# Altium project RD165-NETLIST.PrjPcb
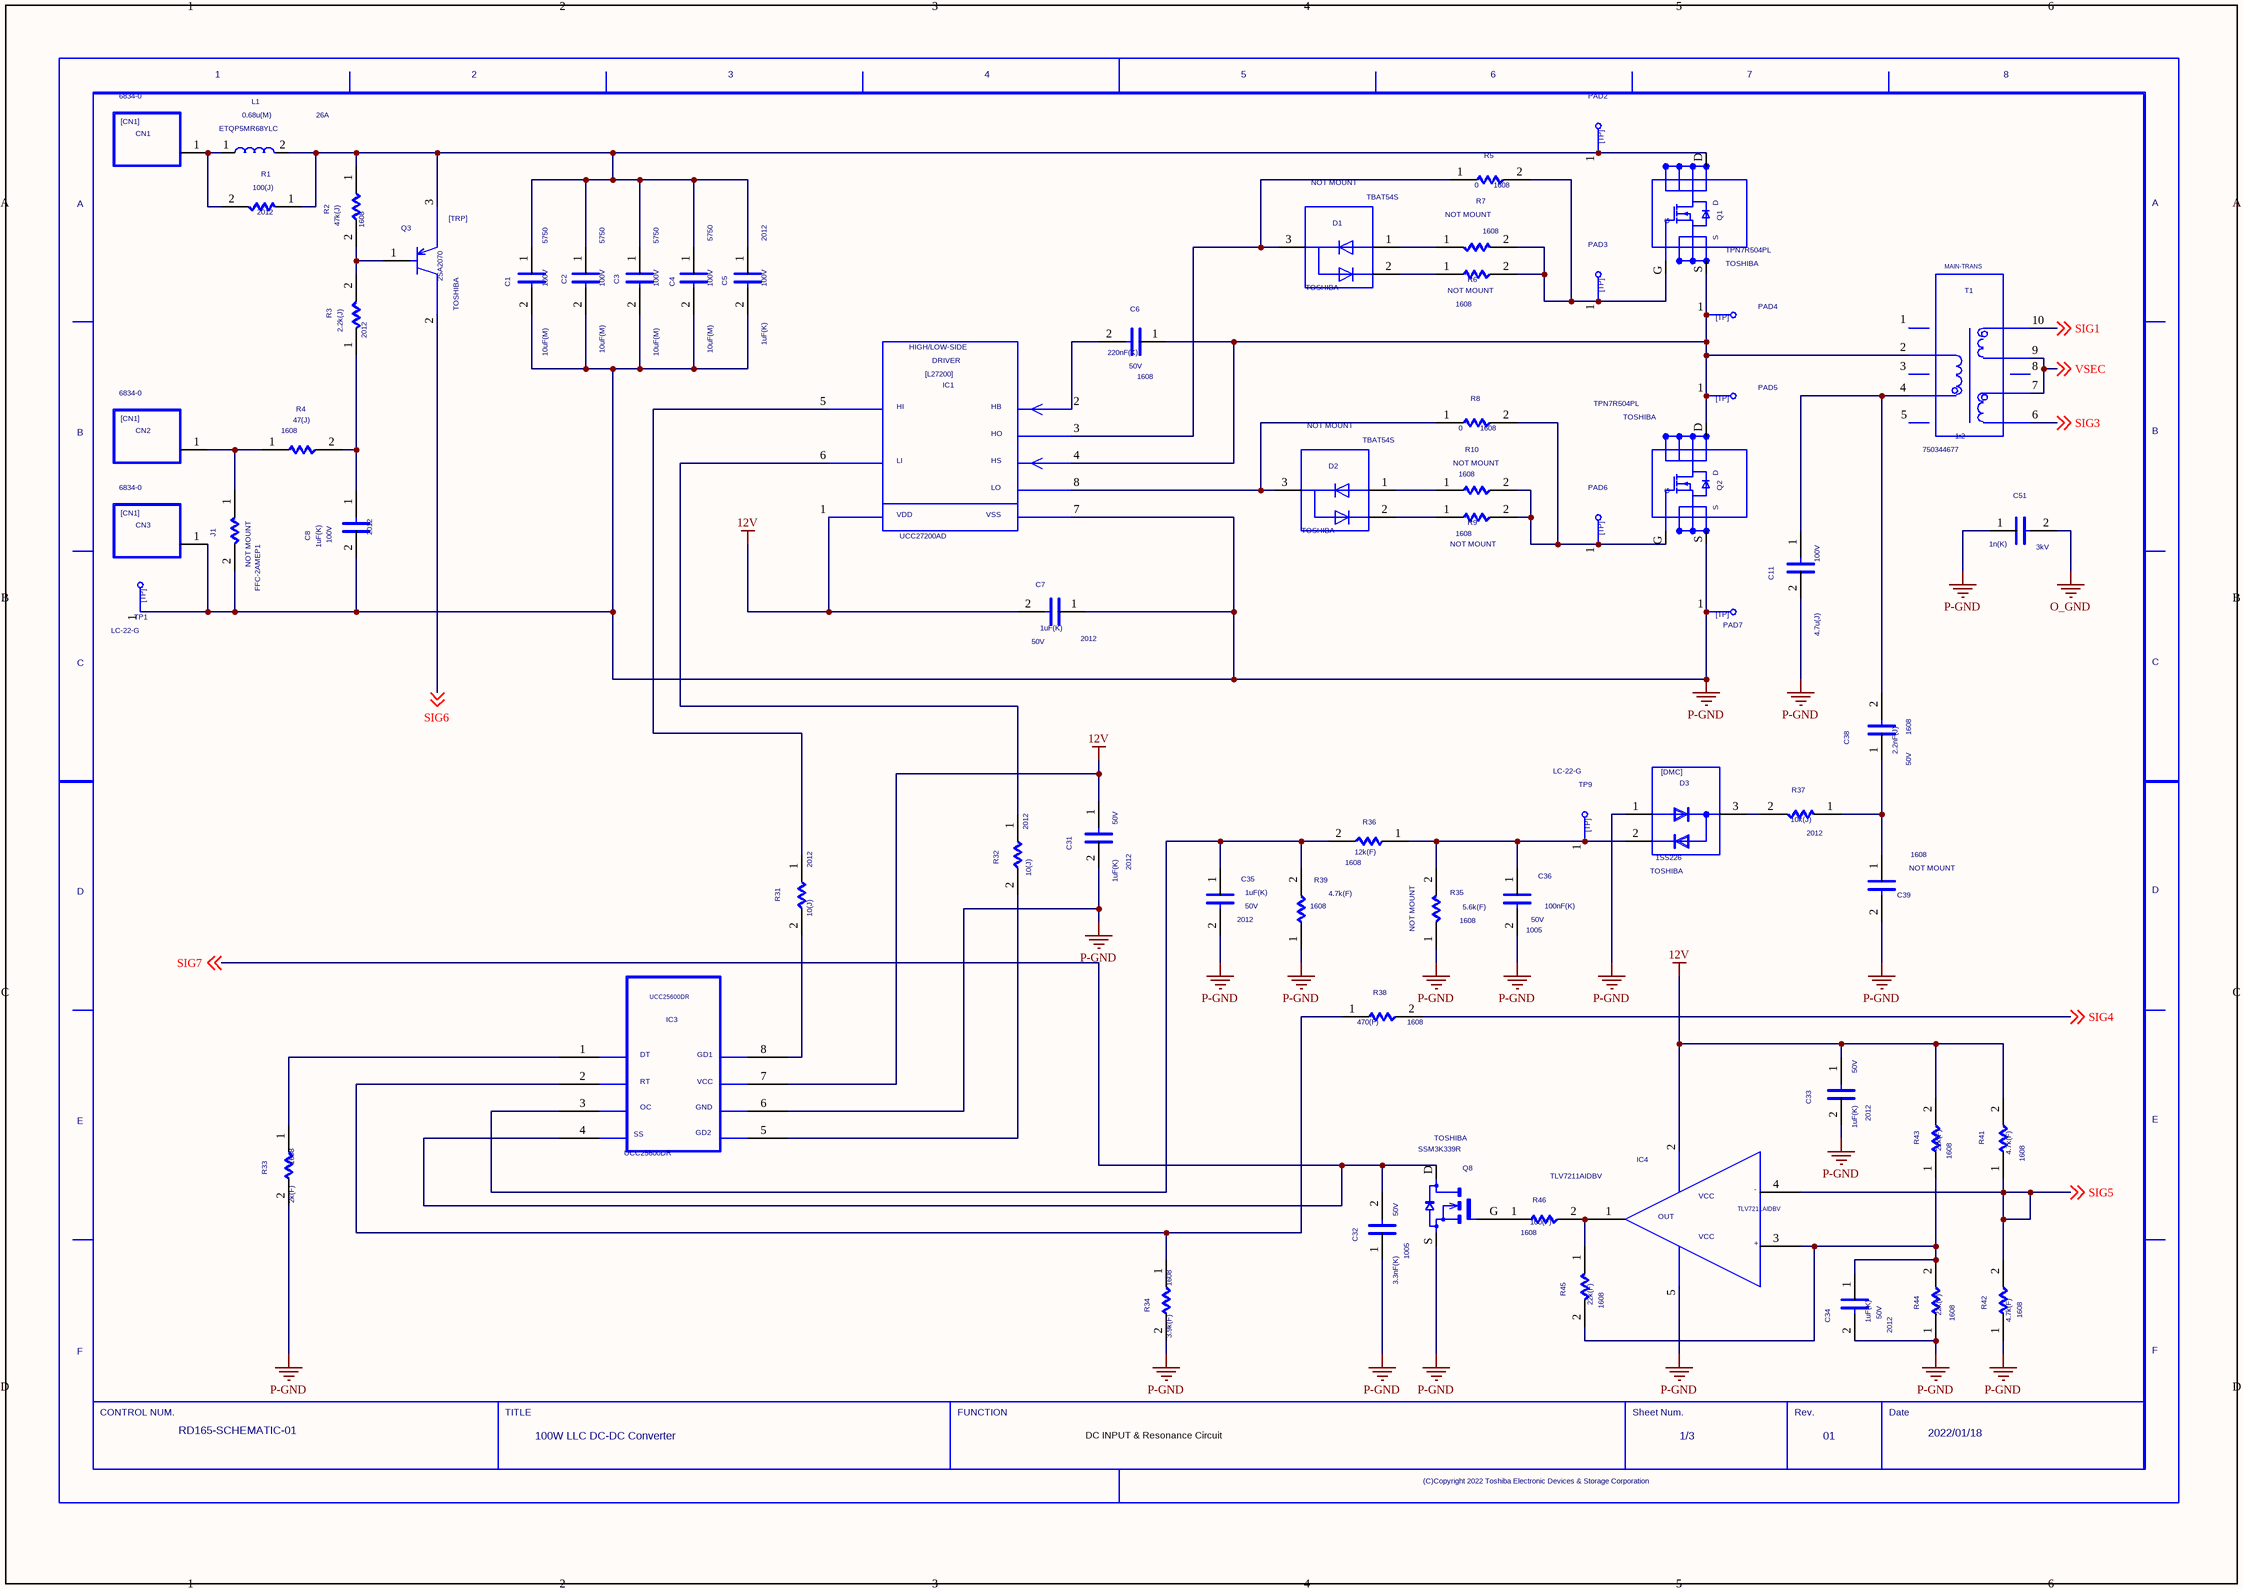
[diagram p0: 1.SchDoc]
3 sheets, 144 parts. Net scope: global (net labels, ports and power ports of the same name join across sheets).
Sheets:
  1.SchDoc
  2.SchDoc
  3.SchDoc

## Sheet 1.SchDoc
size 420 x 297 mm

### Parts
(Parts that share a designator on the sheet are numbered #1, #2 ... from top to bottom, then left to right.)
C1  SIZECODESMD: 5750  VAL2: 100V  VAL1: 10uF(M)  (hidden comment: C)
C2  SIZECODESMD: 5750  VAL2: 100V  VAL1: 10uF(M)  (hidden comment: C)
C3  SIZECODESMD: 5750  VAL2: 100V  VAL1: 10uF(M)  (hidden comment: C)
C4  SIZECODESMD: 5750  VAL2: 100V  VAL1: 10uF(M)  (hidden comment: C)
C5  SIZECODESMD: 2012  VAL2: 100V  VAL1: 1uF(K)  (hidden comment: C)
C6  SIZECODESMD: 1608  VAL2: 50V  VAL1: 220nF(K)  (hidden comment: C)
C7  SIZECODESMD: 2012  VAL2: 50V  VAL1: 1uF(K)  (hidden comment: C)
C8  SIZECODESMD: 2012  VAL2: 100V  VAL1: 1uF(K)  (hidden comment: C)
C11  VAL2: 100V  VAL1: 4.7u(J)  (hidden comment: C)
C31  SIZECODESMD: 2012  VAL2: 50V  VAL1: 1uF(K)  (hidden comment: C)
C32  SIZECODESMD: 1005  VAL2: 50V  VAL1: 3.3nF(K)  (hidden comment: C)
C33  SIZECODESMD: 2012  VAL2: 50V  VAL1: 1uF(K)  (hidden comment: C)
C34  SIZECODESMD: 2012  VAL2: 50V  VAL1: 1uF(K)  (hidden comment: C)
C35  SIZECODESMD: 2012  VAL2: 50V  VAL1: 1uF(K)  (hidden comment: C)
C36  SIZECODESMD: 1005  VAL2: 50V  VAL1: 100nF(K)  (hidden comment: C)
C38  SIZECODESMD: 1608  VAL2: 50V  VAL1: 2.2nF(J)  (hidden comment: C)
C39  NOTMOUNT: NOT MOUNT  SIZECODESMD: 1608  (hidden comment: C)
C51  VAL2: 3kV  VAL1: 1n(K)  (hidden comment: C)
CN1  VAL3: 6834-0  (hidden comment: CN1)
CN2  VAL3: 6834-0  (hidden comment: CN1)
CN3  VAL3: 6834-0  (hidden comment: CN1)
D1  USERCOMPTEXT3: TOSHIBA  NOTMOUNT: NOT MOUNT  (hidden comment: TBAT54S)
D2  USERCOMPTEXT3: TOSHIBA  NOTMOUNT: NOT MOUNT  (hidden comment: TBAT54S)
D3  USERCOMPTEXT3: TOSHIBA  VAL3: 1SS226  (hidden comment: DMC)
IC1  VAL3: UCC27200AD  (hidden comment: L27200)
IC3  UCC25600DR
IC4  TLV7211AIDBV
J1  VAL3: FFC-2AMEP1  NOTMOUNT: NOT MOUNT  (hidden comment: R)
L1  VAL3: ETQP5MR68YLC  VAL2: 26A  VAL1: 0.68u(M)  (hidden comment: L)
PAD2  TP  (value not drawn)
PAD3  TP  (value not drawn)
PAD4  TP  (value not drawn)
PAD5  TP  (value not drawn)
PAD6  TP  (value not drawn)
PAD7  TP  (value not drawn)
Q1  USERCOMPTEXT3: TOSHIBA  VAL3: TPN7R504PL  (hidden comment: TPN7B504PL)
Q2  USERCOMPTEXT3: TOSHIBA  VAL3: TPN7R504PL  (hidden comment: TPN7B504PL)
Q3  USERCOMPTEXT3: TOSHIBA  VAL3: 2SA2070  (hidden comment: TRP)
Q8  USERCOMPTEXT3: TOSHIBA  VAL3: SSM3K339R  (hidden comment: MFNF)
R1  SIZECODESMD: 2012  VAL1: 100(J)  (hidden comment: R)
R2  SIZECODESMD: 1608  VAL1: 47k(J)  (hidden comment: R)
R3  SIZECODESMD: 2012  VAL1: 2.2k(J)  (hidden comment: R)
R4  SIZECODESMD: 1608  VAL1: 47(J)  (hidden comment: R)
R5  SIZECODESMD: 1608  VAL1: 0  (hidden comment: R)
R6  NOTMOUNT: NOT MOUNT  SIZECODESMD: 1608  (hidden comment: R)
R7  NOTMOUNT: NOT MOUNT  SIZECODESMD: 1608  (hidden comment: R)
R8  SIZECODESMD: 1608  VAL1: 0  (hidden comment: R)
R9  NOTMOUNT: NOT MOUNT  SIZECODESMD: 1608  (hidden comment: R)
R10  NOTMOUNT: NOT MOUNT  SIZECODESMD: 1608  (hidden comment: R)
R31  SIZECODESMD: 2012  VAL1: 10(J)  (hidden comment: R)
R32  SIZECODESMD: 2012  VAL1: 10(J)  (hidden comment: R)
R33  SIZECODESMD: 1608  VAL1: 2k(F)  (hidden comment: R)
R34  SIZECODESMD: 1608  VAL1: 3.9k(F)  (hidden comment: R)
R35  NOTMOUNT: NOT MOUNT  SIZECODESMD: 1608  VAL1: 5.6k(F)  (hidden comment: R)
R36  SIZECODESMD: 1608  VAL1: 12k(F)  (hidden comment: R)
R37  SIZECODESMD: 2012  VAL1: 10k(J)  (hidden comment: R)
R38  SIZECODESMD: 1608  VAL1: 470(F)  (hidden comment: R)
R39  SIZECODESMD: 1608  VAL1: 4.7k(F)  (hidden comment: R)
R41  SIZECODESMD: 1608  VAL1: 4.7k(F)  (hidden comment: R)
R42  SIZECODESMD: 1608  VAL1: 4.7k(F)  (hidden comment: R)
R43  SIZECODESMD: 1608  VAL1: 22k(F)  (hidden comment: R)
R44  SIZECODESMD: 1608  VAL1: 22k(F)  (hidden comment: R)
R45  SIZECODESMD: 1608  VAL1: 22k(F)  (hidden comment: R)
R46  SIZECODESMD: 1608  VAL1: 100(F)  (hidden comment: R)
T1  VAL1: 1:2  VAL3: 750344677  (hidden comment: TRANS)
TP1  VAL3: LC-22-G  (hidden comment: TP)
TP9  VAL3: LC-22-G  (hidden comment: TP)
U?#1  DATE: 2022/01/18  TITLE: 100W LLC DC-DC Converter  REVISION: 01  SHEETNUMBER: 1/3  DRAWINGNUMBER: RD165-SCHEMATIC-01  (hidden comment: WAKU_DEF100)

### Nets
O_GND: C51.2
SIG104: C7.2 C31.1 C33.1 IC1.1 IC3.7 IC4.2 R41.2 R43.2  [also labelled 12V, SIG130]
SIG267: C1.2 C2.2 C3.2 C4.2 C5.2 C7.1 C8.2 C11.2 C31.2 C32.1 C33.2 C34.2 C35.2 C36.2 C39.2 C51.1 CN3.1 D3.1(A) IC1.7 IC3.6 IC4.5 J1.2 PAD7.1 Q2.S Q8.S R33.2 R34.2 R35.1 R39.1 R42.1 R44.1 TP1.1  [also labelled P-GND, SIG268]
SIG270: T1.7 T1.9 ; off-sheet VSEC  [also labelled VSEC]  [project net SIG214]
DN000002: IC3.2 R34.1 R38.1
DN000007: C11.1 C38.2 T1.4
DN000046: IC3.1 R33.1
N04422: C1.1 C2.1 C3.1 C4.1 C5.1 L1.2 PAD2.1 Q1.D Q3.3(E) R1.1 R2.1
N216469: Q3.1(B) R2.2 R3.2
N216829: C8.1 R3.1 R4.2
N216837: CN2.1 J1.1 R4.1
SIG1: T1.10 ; off-sheet SIG1
SIG3: T1.6 ; off-sheet SIG3
SIG4: R38.2 ; off-sheet SIG4
SIG5: IC4.4 R41.1 R42.2 ; off-sheet SIG5
SIG6: Q3.2(C) ; off-sheet SIG6
SIG7: C32.2 IC3.4 Q8.D ; off-sheet SIG7
SIG67: IC3.8 R31.2
SIG85: C34.1 IC4.3 R43.1 R44.2 R45.2
SIG102: C38.1 C39.1 R37.1
SIG119: CN1.1 L1.1 R1.2
SIG125: D2.3 IC1.8 R8.1
SIG126: IC1.6 R32.1
SIG127: IC1.5 R31.1
SIG128: D1.3 IC1.3 R5.1
SIG129: C6.2 IC1.2
SIG131: C6.1 IC1.4 PAD4.1 PAD5.1 Q1.S Q2.D T1.2
SIG190: IC3.5 R32.2
SIG212: D3.3(AC) R37.2
SIG218: PAD3.1 Q1.G R5.2 R6.2 R7.2
SIG231: PAD6.1 Q2.G R8.2 R9.2 R10.2
SIG233: C36.1 D3.2(C) R35.2 R36.1 TP9.1
SIG237: D2.1 R10.1
SIG239: D1.2 R6.1
SIG240: IC4.1 R45.1 R46.2
SIG248: D1.1 R7.1
SIG249: D2.2 R9.1
SIG269: C35.1 IC3.3 R36.2 R39.2
NetQ8_G: Q8.G R46.1

Not connected (* = marked no-connect by the designer): T1 1 3 5 8

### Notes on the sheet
- DC INPUT & Resonance Circuit

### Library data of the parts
C1-C4 = C: OriginalSymbolOrigin: (2540,7620); RATEDVOLTAGE: 50; MAXGCOUNT: 1; TEMPCHARACTERI2: E; OUMEMAKER: KYC 京セラ; QUADMODEL: CON_10U; FNLEADFREETHET1GT2GMCTH1: N_N_N; OUMECLASSIFICATION: セラミックコンデンサ; CDBNAME: Chip5750_TD; NOMINALCAPACITA: 10u; OUMEMAKERKATAMEI: CX55Y5U106M50AT; CAPACITANCETOLE: M; CDMASTERCADCELG: DC848R; ADSMODELNAME: s_CX55Y5U106M50AT
C5 = C: OriginalSymbolOrigin: (2540,7620); RATEDVOLTAGE: 100; MAXGCOUNT: 1; OUMEMAKER: TDK ＴＤＫ; QUADMODEL: CON_1U; FNLEADFREETHET1GT2GMCTH1: 3_2_N; OUMECLASSIFICATION: セラミックコンデンサ; CDBNAME: Chip2012_GS_1; NOMINALCAPACITA: 1u; PMPRODUCTSTYPEG: HEV; OUMEMAKERKATAMEI: CGA4J3X7S2A105KT@@; CAPACITANCETOLE: K; CDMASTERCADCELG: KC0136; ADSMODELNAME: s_CGA4J3X7S2A105KT@@
C6 = C: OriginalSymbolOrigin: (2540,7620); RATEDVOLTAGE: 50; MAXGCOUNT: 1; OUMEMAKER: TDK ＴＤＫ; QUADMODEL: CON_220N; FNLEADFREETHET1GT2GMCTH1: N_N_N; OUMECLASSIFICATION: セラミックコンデンサ; CDBNAME: Chip1608_GS_1; NOMINALCAPACITA: 220n; PMPRODUCTSTYPEG: DA; OUMEMAKERKATAMEI: CGA3E3X7R1H224KT@@; CAPACITANCETOLE: K; CDMASTERCADCELG: KCK0238; ADSMODELNAME: s_CGA3E3X7R1H224KT@@
C7 C34 = C: OriginalSymbolOrigin: (2540,7620); RATEDVOLTAGE: 50; MAXGCOUNT: 1; OUMEMAKER: TDK ＴＤＫ; QUADMODEL: CON_1U; FNLEADFREETHET1GT2GMCTH1: 3_2_N; OUMECLASSIFICATION: セラミックコンデンサ; CDBNAME: Chip2012_GS_1; NOMINALCAPACITA: 1u; PMPRODUCTSTYPEG: DA; OUMEMAKERKATAMEI: CGA4J3X7R1H105KT@@; CAPACITANCETOLE: K; CDMASTERCADCELG: KC0159; ADSMODELNAME: s_CGA4J3X7R1H105KT@@
C8 C31 = C#1: OriginalSymbolOrigin: (2540,7620); CaptureCellPackProp: C##1; RATEDVOLTAGE: 50; MAXGCOUNT: 1; OUMEMAKER: TDK ＴＤＫ; QUADMODEL: CON_1U; FNLEADFREETHET1GT2GMCTH1: 3_2_N; OUMECLASSIFICATION: セラミックコンデンサ; CDBNAME: Chip2012_GS_1; NOMINALCAPACITA: 1u; PMPRODUCTSTYPEG: DA; OUMEMAKERKATAMEI: CGA4J3X7R1H105KT@@; CAPACITANCETOLE: K; CDMASTERCADCELG: KC0159; ADSMODELNAME: s_CGA4J3X7R1H105KT@@
C11 = C#1: OriginalSymbolOrigin: (2540,7620); CaptureCellPackProp: C##1; CDBNAME: CB182E0475***_AV
C32 = C: OriginalSymbolOrigin: (2540,7620); RATEDVOLTAGE: 50; MAXGCOUNT: 1; OUMEMAKER: TDK ＴＤＫ; QUADMODEL: CON_10N; FNLEADFREETHET1GT2GMCTH1: 3_0_N; OUMECLASSIFICATION: セラミックコンデンサ; CDBNAME: Chip1005_GS_2; NOMINALCAPACITA: 10n; PMPRODUCTSTYPEG: DA; OUMEMAKERKATAMEI: CGA2B3X7R1H103KT@@; CAPACITANCETOLE: K; CDMASTERCADCELG: KC0154; ADSMODELNAME: s_CGA2B3X7R1H103KT@@
C33 = C#1: OriginalSymbolOrigin: (2540,7620); CaptureCellPackProp: C##1; RATEDVOLTAGE: 50; MAXGCOUNT: 1; OUMEMAKER: TDK ＴＤＫ; QUADMODEL: CON_1U; FNLEADFREETHET1GT2GMCTH1: 3_2_N; OUMECLASSIFICATION: セラミックコンデンサ; CDBNAME: Chip2012_GS_1; NOMINALCAPACITA: 1u; PMPRODUCTSTYPEG: DA; OUMEMAKERKATAMEI: CGA4J3X7R1H105KTXXXS@@; CAPACITANCETOLE: K; CDMASTERCADCELG: KC0187; ADSMODELNAME: s_CGA4J3X7R1H105KTXXXS@@
C35 = C: OriginalSymbolOrigin: (2540,7620); CDBNAME: Chip2012_GS_1
C36 = C: OriginalSymbolOrigin: (2540,7620); CDBNAME: Chip1005_GS_2
C38 = C: OriginalSymbolOrigin: (2540,7620); RATEDVOLTAGE: 50; MAXGCOUNT: 1; OUMEMAKER: MRT 村田製作所; QUADMODEL: CON_2.2N; FNLEADFREETHET1GT2GMCTH1: 3_2_N; OUMECLASSIFICATION: セラミックコンデンサ; CDBNAME: Chip1608_GS_1; NOMINALCAPACITA: 2.2n; PMPRODUCTSTYPEG: HEV; OUMEMAKERKATAMEI: GCM1885C1H222JA16D@@; CAPACITANCETOLE: J; CDMASTERCADCELG: KC0134; ADSMODELNAME: s_GCM1885C1H222JA16D@@
C39 = C: OriginalSymbolOrigin: (2540,7620); RATEDVOLTAGE: 50; MAXGCOUNT: 1; OUMEMAKER: TDK ＴＤＫ; QUADMODEL: CON_10N; FNLEADFREETHET1GT2GMCTH1: 3_2_N; OUMECLASSIFICATION: セラミックコンデンサ; CDBNAME: Chip1608_GS_1; NOMINALCAPACITA: 10n; PMPRODUCTSTYPEG: HEV; OUMEMAKERKATAMEI: CGA3E2C0G1H103JT@@; VAL2: 50V; VAL1: 10nF(J); CAPACITANCETOLE: J; CDMASTERCADCELG: KC0134; ADSMODELNAME: s_CGA3E2C0G1H103JT@@
C51 = C: OriginalSymbolOrigin: (2540,7620); CDBNAME: Chip4632_AV
CN1-CN3 = CN1: OUMEPARTTYPE: CN; OriginalSymbolOrigin: (2540,12700); RATEDVOLTAGE: 0; MAXGCOUNT: 1; PLUGDIAMETER: 6m; OUMEMAKER: SMK エスエャPイ; FNLEADFREETHET1GT2GMCTH1: 9_1_N; OUMECLASSIFICATION: 単頭プラグ; CDBNAME: 6834-0-00-**-00-00-03-0_ML; OUMEMAKERKATAMEI: CMI1501-0101; CDMASTERCADCELG: CU0059
D1 D2 = TBAT54S: SAVEAREA0: -9930,-5308,32601,25918; TIME: 14:49:55; UPDATEUSER: t5459927; UPDATETIME: 18:16:07; SAVECOUNT: 5; OriginalSymbolOrigin: (5080,17780); CDBNAME: TBAT54S_TS
D3 = DMC: OUMEPARTTYPE: D; OriginalSymbolOrigin: (5080,20320); FORWARDVOLTAGEM: 0; MAXREVERSEVOLTA: 70; MAXGCOUNT: 1; OUMEMAKER: TSB 東芝; MOUNTINGFORMSMD: SMD; FNLEADFREETHET1GT2GMCTH1: 2_0_N; OUMECLASSIFICATION: 小信号ダイオード; CDBNAME: 1SS226_TS; PMPRODUCTSTYPEG: PC1; OUMEMAKERKATAMEI: 1SS226(TE85R); CDMASTERCADCELG: DD902A; ADSMODELNAME: s_1SS226_TE85R_
IC1 = L27200: OUMEPARTTYPE: IC; SAVEAREA0: -11719,-442,57445,43603; SAVECOUNT: 88; TIME: 14:04:55; UPDATEUSER: 19910145; UPDATETIME: 08:40:41; OriginalSymbolOrigin: (0,40640); MAXGCOUNT: 1; OUMEMAKER: TII テキサスインスツルメンツ; MOUNTINGFORMSMD: SMD; FNLEADFREETHET1GT2GMCTH1: N_N_N; OUMECLASSIFICATION: その他; CDBNAME: UCC272**AD_TI; OUMEMAKERKATAMEI: UCC27200D; CDMASTERCADCELG: I810D8; KIND: OTHER
IC3 = UCC25600DR: SAVEAREA0: -5309,-792,48736,38830; TIME: 17:00:15; UPDATEUSER: t5459927; UPDATETIME: 08:35:41; SAVECOUNT: 3; OriginalSymbolOrigin: (7620,35560); CDBNAME: UCC25600D*_TI
IC4 = TLV7211AIDBV: SAVECOUNT: 19; SAVEAREA0: -11523,-10867,52370,35975; TIME: 20:02:00; UPDATEUSER: t5459927; UPDATETIME: 08:40:37; OriginalSymbolOrigin: (7620,25400); CDBNAME: TLV7211AIDBVR_TI
J1 = R: OriginalSymbolOrigin: (5080,5080); CDBNAME: FFC-2AMEP1_HN
L1 = L: OriginalSymbolOrigin: (2540,5080); CDBNAME: ETQP5M***YLC_PN
PAD2-PAD7 = TP: TIME: 16:12:21; UPDATEUSER: fukuda-y; UPDATETIME: 16:18:11; SAVECOUNT: 2; SAVEAREA0: -242,-92,12810,7836; OriginalSymbolOrigin: (0,7620); CDBNAME: TP_I_TH0.5_LC1.1_RC1.2_GS
Q1 Q2 = TPN7B504PL: SAVEAREA0: -19342,-136,26697,27151; TIME: 18:57:44; UPDATEUSER: t5459927; UPDATETIME: 14:39:22; SAVECOUNT: 22; OriginalSymbolOrigin: (2540,20320); CDBNAME: TPN7R504PL_TS_A
Q3 = TRP: OUMEPARTTYPE: Q; TIME: 09:39:04; UPDATEUSER: 19870035; UPDATETIME: 15:34:42; SAVECOUNT: 12; SAVEAREA0: -5466,-244,29263,20886; OriginalSymbolOrigin: (5080,22860); MAXGCOUNT: 1; OUMEMAKER: TSB 東芝; MOUNTINGFORMSMD: SMD; FNLEADFREETHET1GT2GMCTH1: N_N_N; OUMECLASSIFICATION: PNPバイポーラトランジスタ; CDBNAME: 2SA2070_TS; PMPRODUCTSTYPEG: HD1; MAXGDVOLTAGE: 0; OUMEMAKERKATAMEI: 2SA2070(TE12L,F); CDMASTERCADCELG: DQ901D; ADSMODELNAME: s_2SA2070_TE12L_F_; MAXCOLLECTORCUR: -1
Q8 = MFNF: SAVECOUNT: 13; SAVEAREA0: -36202,-24391,51351,39797; TIME: 17:06:19; UPDATEUSER: t5459927; UPDATETIME: 17:07:36; OriginalSymbolOrigin: (5080,12700); CDBNAME: SSM3K339R_TS_A
R1 = R: OriginalSymbolOrigin: (5080,5080); MAXGCOUNT: 1; OUMEMAKER: NAE パナソニックエレクトロニックデバイス; QUADMODEL: RES_100; MOUNTINGFORMSMD: SMD; FNLEADFREETHET1GT2GMCTH1: 2_2_N; OUMECLASSIFICATION: 表面実装用固定抵抗器; CDBNAME: Chip2012_GS_1; RESISTANCETOLER: J; PMPRODUCTSTYPEG: PC1-PCS; POWERRATING: 250m; OUMEMAKERKATAMEI: ERJP06J101V; NOMINALRESISTAN: 100; VAL2: 400mW; CDMASTERCADCELG: KC0006; ADSMODELNAME: s_ERJP06J101V
R2 = R: OriginalSymbolOrigin: (5080,5080); MAXGCOUNT: 1; OUMEMAKER: NAE パナソニックエレクトロニックデバイス; QUADMODEL: RES_47K; MOUNTINGFORMSMD: SMD; FNLEADFREETHET1GT2GMCTH1: 3_2_N; OUMECLASSIFICATION: 表面実装用固定抵抗器; CDBNAME: Chip1608_GS_1; RESISTANCETOLER: J; PMPRODUCTSTYPEG: HEV; POWERRATING: 100m; OUMEMAKERKATAMEI: ERJ3GEYJ473V@@; NOMINALRESISTAN: 47K; VAL2: 100mW; CDMASTERCADCELG: KC0133; ADSMODELNAME: s_ERJ3GEYJ473V@@
R3 = R: OriginalSymbolOrigin: (5080,5080); MAXGCOUNT: 1; OUMEMAKER: KOA コーア; QUADMODEL: RES_2.2K; MOUNTINGFORMSMD: SMD; FNLEADFREETHET1GT2GMCTH1: 3_1_N; OUMECLASSIFICATION: 表面実装用固定抵抗器; CDBNAME: Chip2012_GS_1; RESISTANCETOLER: J; PMPRODUCTSTYPEG: HEV; POWERRATING: 250m; OUMEMAKERKATAMEI: SG73P2ATTD222J@@; NOMINALRESISTAN: 2.2K; VAL2: 400mW; CDMASTERCADCELG: KC0135; ADSMODELNAME: s_SG73P2ATTD222J@@
R4 = R: OriginalSymbolOrigin: (5080,5080); MAXGCOUNT: 1; OUMEMAKER: KOA コーア; QUADMODEL: RES_47; MOUNTINGFORMSMD: SMD; FNLEADFREETHET1GT2GMCTH1: 3_1_N; OUMECLASSIFICATION: 表面実装用固定抵抗器; CDBNAME: Chip1608_GS_1; RESISTANCETOLER: J; PMPRODUCTSTYPEG: HEV; POWERRATING: 100m; OUMEMAKERKATAMEI: RK73B1JTTD470J@@; NOMINALRESISTAN: 47; VAL2: 100mW; CDMASTERCADCELG: KC0133; ADSMODELNAME: s_RK73B1JTTD470J@@
R5 R8 = R: OriginalSymbolOrigin: (5080,5080); VAL2: 100mW; MAXGCOUNT: 1; OUMEMAKER: HDK 北陸電気工業; QUADMODEL: RES_0; MOUNTINGFORMSMD: SMD; FNLEADFREETHET1GT2GMCTH1: 2_1_N; OUMECLASSIFICATION: 表面実装用固定抵抗器; CDBNAME: Chip1608_GS_1; RESISTANCETOLER: X; PMPRODUCTSTYPEG: HD1; POWERRATING: 100m; OUMEMAKERKATAMEI: CR1/16 000V HSF; CDMASTERCADCELG: KC0167; ADSMODELNAME: s_CR1_16_000V_HSF
R6 R9 R10 = R: OriginalSymbolOrigin: (5080,5080); MAXGCOUNT: 1; OUMEMAKER: NAE パナソニックエレクトロニックデバイス; QUADMODEL: RES_10; MOUNTINGFORMSMD: SMD; FNLEADFREETHET1GT2GMCTH1: 3_1_N; OUMECLASSIFICATION: 表面実装用固定抵抗器; CDBNAME: Chip1608_GS_1; RESISTANCETOLER: F; POWERRATING: 63m; OUMEMAKERKATAMEI: ERJ3GEYF100V; NOMINALRESISTAN: 10; VAL2: 100mW; VAL1: 10(F); CDMASTERCADCELG: DR802R; ADSMODELNAME: s_ERJ3GEYF100V
R7 = R#1: OriginalSymbolOrigin: (5080,5080); CaptureCellPackProp: R##1; MAXGCOUNT: 1; OUMEMAKER: NAE パナソニックエレクトロニックデバイス; QUADMODEL: RES_10; MOUNTINGFORMSMD: SMD; FNLEADFREETHET1GT2GMCTH1: 3_1_N; OUMECLASSIFICATION: 表面実装用固定抵抗器; CDBNAME: Chip1608_GS_1; RESISTANCETOLER: F; POWERRATING: 63m; OUMEMAKERKATAMEI: ERJ3GEYF100V; NOMINALRESISTAN: 10; VAL2: 100mW; VAL1: 10(F); CDMASTERCADCELG: DR802R; ADSMODELNAME: s_ERJ3GEYF100V
R31 R32 = R: OriginalSymbolOrigin: (5080,5080); MAXGCOUNT: 1; OUMEMAKER: NAE パナソニックエレクトロニックデバイス; QUADMODEL: RES_10; MOUNTINGFORMSMD: SMD; FNLEADFREETHET1GT2GMCTH1: N_N_N; OUMECLASSIFICATION: 表面実装用固定抵抗器; CDBNAME: Chip2012_GS_1; RESISTANCETOLER: J; PMPRODUCTSTYPEG: SV1; POWERRATING: 125m; OUMEMAKERKATAMEI: (SV)ERJ6GEYJ100V; NOMINALRESISTAN: 10; VAL2: 400mW; CDMASTERCADCELG: KCK0273; ADSMODELNAME: s__SV_ERJ6GEYJ100V
R33 = R#1: OriginalSymbolOrigin: (5080,5080); CaptureCellPackProp: R##1; MAXGCOUNT: 1; OUMEMAKER: KOA コーア; QUADMODEL: RES_2K; MOUNTINGFORMSMD: SMD; FNLEADFREETHET1GT2GMCTH1: 3_1_N; OUMECLASSIFICATION: 表面実装用固定抵抗器; CDBNAME: Chip1608_GS_1; RESISTANCETOLER: F; PMPRODUCTSTYPEG: HEV; POWERRATING: 100m; OUMEMAKERKATAMEI: RK73H1JTTD2001F@@; NOMINALRESISTAN: 2K; VAL2: 100mW; CDMASTERCADCELG: KC0133; ADSMODELNAME: s_RK73H1JTTD2001F@@
R34 = R#1: OriginalSymbolOrigin: (5080,5080); CaptureCellPackProp: R##1; MAXGCOUNT: 1; OUMEMAKER: ROH ロー・; QUADMODEL: RES_3.9K; MOUNTINGFORMSMD: SMD; FNLEADFREETHET1GT2GMCTH1: 3_1_N; OUMECLASSIFICATION: 表面実装用固定抵抗器; CDBNAME: Chip1608_GS_1; RESISTANCETOLER: F; POWERRATING: 63m; OUMEMAKERKATAMEI: MCR03EZPFX3901; NOMINALRESISTAN: 3.9K; VAL2: 100mw; CDMASTERCADCELG: DR802R; ADSMODELNAME: s_MCR03EZPFX3901
R35 = R#1: OriginalSymbolOrigin: (5080,5080); CaptureCellPackProp: R##1; VAL2: 100mw; MAXGCOUNT: 1; OUMEMAKER: HDK 北陸電気工業; QUADMODEL: RES_7.5K; MOUNTINGFORMSMD: SMD; FNLEADFREETHET1GT2GMCTH1: 3_1_N; OUMECLASSIFICATION: 表面実装用固定抵抗器; CDBNAME: Chip1608_GS_1; RESISTANCETOLER: F; POWERRATING: 63m; OUMEMAKERKATAMEI: CR1/16 752FV; NOMINALRESISTAN: 7.5K; CDMASTERCADCELG: DR802R; ADSMODELNAME: s_CR1_16_752FV
R36 R39 = R: OriginalSymbolOrigin: (5080,5080); CDBNAME: Chip1608_GS_1
R37 = R: OriginalSymbolOrigin: (5080,5080); MAXGCOUNT: 1; OUMEMAKER: KOA コーア; QUADMODEL: RES_10K; MOUNTINGFORMSMD: SMD; FNLEADFREETHET1GT2GMCTH1: N_N_N; OUMECLASSIFICATION: 表面実装用固定抵抗器; CDBNAME: Chip2012_GS_1; RESISTANCETOLER: J; PMPRODUCTSTYPEG: DME; POWERRATING: 250m; OUMEMAKERKATAMEI: SG73S2ATTD103J; NOMINALRESISTAN: 10K; VAL2: 400mW; CDMASTERCADCELG: KC0006; ADSMODELNAME: s_SG73S2ATTD103J
R38 = R: OriginalSymbolOrigin: (5080,5080); MAXGCOUNT: 1; OUMEMAKER: KOA コーア; QUADMODEL: RES_470; MOUNTINGFORMSMD: SMD; FNLEADFREETHET1GT2GMCTH1: N_N_N; OUMECLASSIFICATION: 表面実装用固定抵抗器; CDBNAME: Chip1608_GS_1; RESISTANCETOLER: F; PMPRODUCTSTYPEG: DME; POWERRATING: 100m; OUMEMAKERKATAMEI: RK73H1JRTTD4700F; NOMINALRESISTAN: 470; VAL2: 100mW; CDMASTERCADCELG: KC0008; ADSMODELNAME: s_RK73H1JRTTD4700F
R41 R42 = R: OriginalSymbolOrigin: (5080,5080); MAXGCOUNT: 1; OUMEMAKER: NAE パナソニックエレクトロニックデバイス; QUADMODEL: RES_4.7K; MOUNTINGFORMSMD: SMD; FNLEADFREETHET1GT2GMCTH1: N_N_N; OUMECLASSIFICATION: 表面実装用固定抵抗器; CDBNAME: Chip1608_GS_1; RESISTANCETOLER: F; PMPRODUCTSTYPEG: DA; POWERRATING: 100m; OUMEMAKERKATAMEI: ERJ3EKF4701V@@; NOMINALRESISTAN: 4.7K; VAL2: 100mW; CDMASTERCADCELG: KCK0234; ADSMODELNAME: s_ERJ3EKF4701V@@
R43-R45 = R: OriginalSymbolOrigin: (5080,5080); MAXGCOUNT: 1; OUMEMAKER: NAE パナソニックエレクトロニックデバイス; QUADMODEL: RES_22K; MOUNTINGFORMSMD: SMD; FNLEADFREETHET1GT2GMCTH1: N_N_N; OUMECLASSIFICATION: 表面実装用固定抵抗器; CDBNAME: Chip1608_GS_1; RESISTANCETOLER: F; POWERRATING: 100m; OUMEMAKERKATAMEI: ERJ3EKF2202V; NOMINALRESISTAN: 22K; VAL2: 100mW; CDMASTERCADCELG: KC0008; ADSMODELNAME: s_ERJ3EKF2202V
R46 = R: OriginalSymbolOrigin: (5080,5080); MAXGCOUNT: 1; OUMEMAKER: KOA コーア; QUADMODEL: RES_100; MOUNTINGFORMSMD: SMD; FNLEADFREETHET1GT2GMCTH1: 3_1_N; OUMECLASSIFICATION: 表面実装用固定抵抗器; CDBNAME: Chip1608_GS_1; RESISTANCETOLER: F; POWERRATING: 63m; OUMEMAKERKATAMEI: RK73H1JTD1000F; NOMINALRESISTAN: 100; VAL2: 100mW; CDMASTERCADCELG: DR802R; ADSMODELNAME: s_RK73H1JTD1000F
T1 = TRANS: TIME: 11:13:20; UPDATEUSER: t5459927; UPDATETIME: 08:41:46; SAVECOUNT: 10; SAVEAREA0: -21734,-9489,47855,41529; OriginalSymbolOrigin: (-2540,33020); CDBNAME: PC40EER28_GS
TP1 TP9 = TP: TIME: 16:12:21; UPDATEUSER: fukuda-y; UPDATETIME: 16:18:11; SAVECOUNT: 2; SAVEAREA0: -242,-92,12810,7836; OriginalSymbolOrigin: (0,7620); CDBNAME: LC-22_GS
U?#1 = WAKU_DEF100: PLOTTIME: HH:MM; SAVEAREA0: 198008,-65938,436964,90161; TIME: 14:30:25; UPDATEUSER: t5459927; UPDATETIME: 11:00:47; SAVECOUNT: 4; OriginalSymbolOrigin: (10160,284480)

## Sheet 2.SchDoc
size 420 x 297 mm
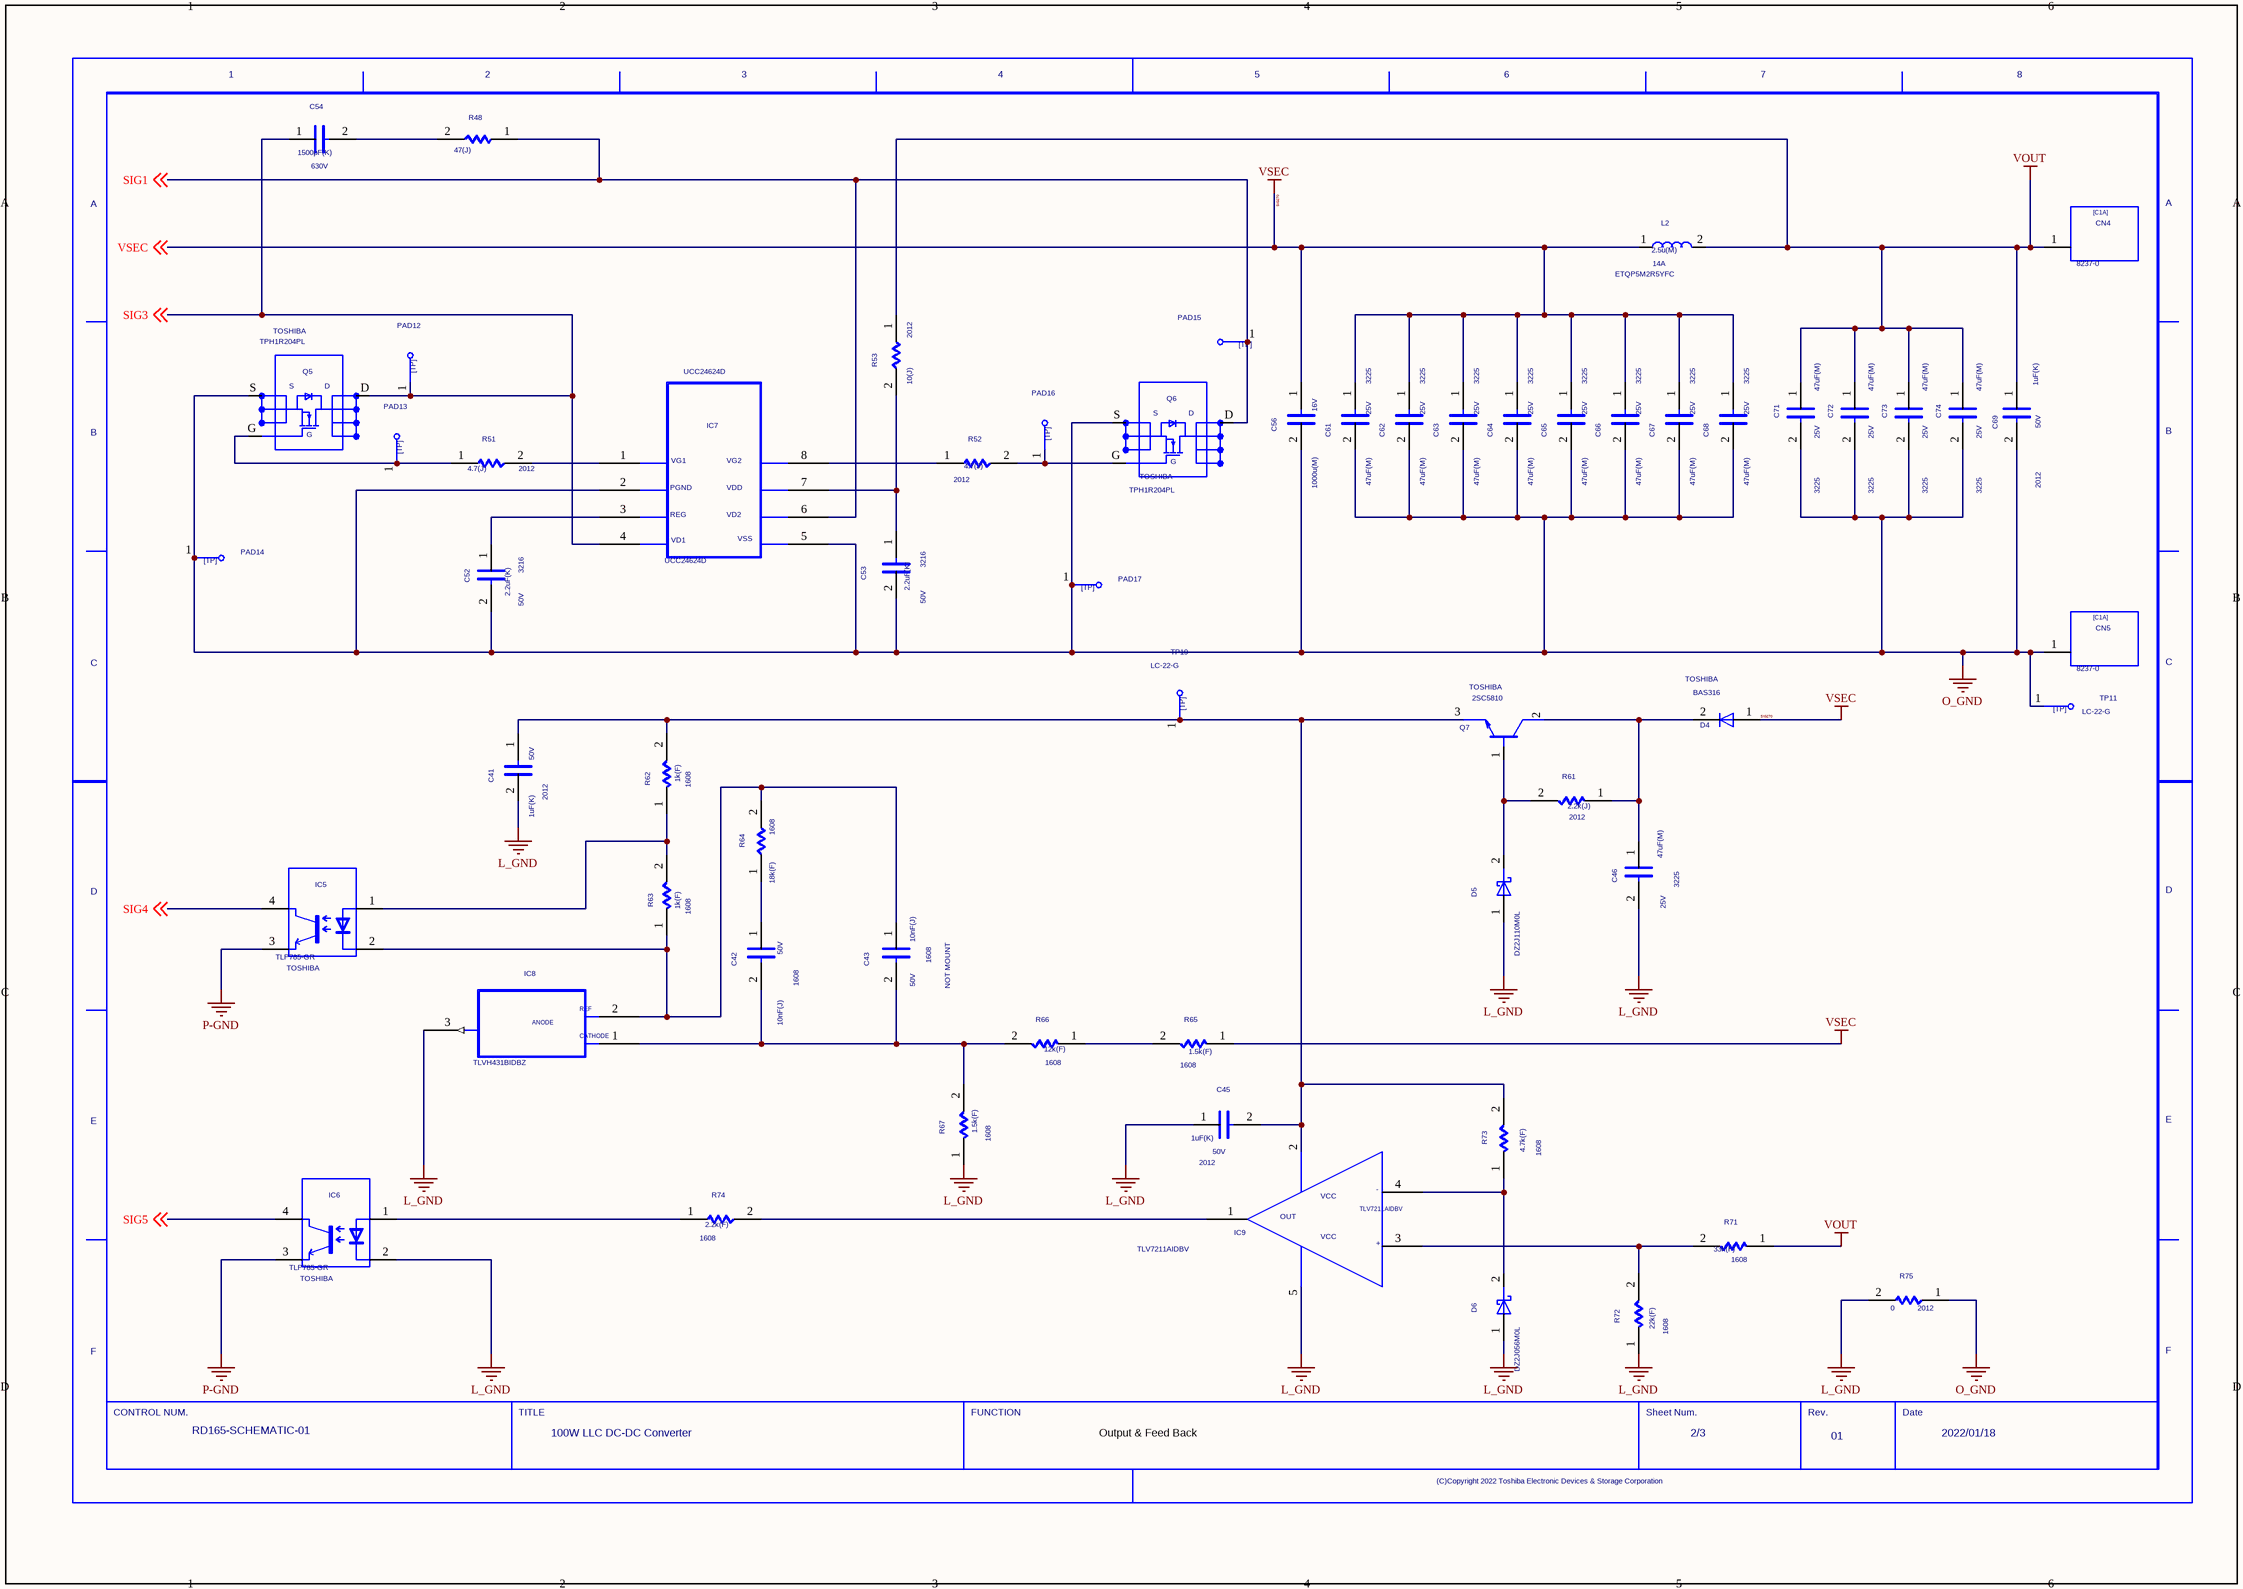
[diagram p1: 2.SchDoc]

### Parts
(Parts that share a designator on the sheet are numbered #1, #2 ... from top to bottom, then left to right.)
C41  SIZECODESMD: 2012  VAL2: 50V  VAL1: 1uF(K)  (hidden comment: C)
C42  SIZECODESMD: 1608  VAL2: 50V  VAL1: 10nF(J)  (hidden comment: C)
C43  NOTMOUNT: NOT MOUNT  SIZECODESMD: 1608  VAL2: 50V  VAL1: 10nF(J)  (hidden comment: C)
C45  SIZECODESMD: 2012  VAL2: 50V  VAL1: 1uF(K)  (hidden comment: C)
C46  SIZECODESMD: 3225  VAL2: 25V  VAL1: 47uF(M)  (hidden comment: C)
C52  SIZECODESMD: 3216  VAL2: 50V  VAL1: 2.2uF(K)  (hidden comment: C)
C53  SIZECODESMD: 3216  VAL2: 50V  VAL1: 2.2uF(K)  (hidden comment: C)
C54  VAL2: 630V  VAL1: 1500pF(K)  (hidden comment: C)
C56  VAL2: 16V  VAL1: 1000u(M)  (hidden comment: C)
C61  SIZECODESMD: 3225  VAL2: 25V  VAL1: 47uF(M)  (hidden comment: C)
C62  SIZECODESMD: 3225  VAL2: 25V  VAL1: 47uF(M)  (hidden comment: C)
C63  SIZECODESMD: 3225  VAL2: 25V  VAL1: 47uF(M)  (hidden comment: C)
C64  SIZECODESMD: 3225  VAL2: 25V  VAL1: 47uF(M)  (hidden comment: C)
C65  SIZECODESMD: 3225  VAL2: 25V  VAL1: 47uF(M)  (hidden comment: C)
C66  SIZECODESMD: 3225  VAL2: 25V  VAL1: 47uF(M)  (hidden comment: C)
C67  SIZECODESMD: 3225  VAL2: 25V  VAL1: 47uF(M)  (hidden comment: C)
C68  SIZECODESMD: 3225  VAL2: 25V  VAL1: 47uF(M)  (hidden comment: C)
C69  SIZECODESMD: 2012  VAL2: 50V  VAL1: 1uF(K)  (hidden comment: C)
C71  SIZECODESMD: 3225  VAL2: 25V  VAL1: 47uF(M)  (hidden comment: C)
C72  SIZECODESMD: 3225  VAL2: 25V  VAL1: 47uF(M)  (hidden comment: C)
C73  SIZECODESMD: 3225  VAL2: 25V  VAL1: 47uF(M)  (hidden comment: C)
C74  SIZECODESMD: 3225  VAL2: 25V  VAL1: 47uF(M)  (hidden comment: C)
CN4  VAL3: 8237-0  (hidden comment: C1A)
CN5  VAL3: 8237-0  (hidden comment: C1A)
D4  USERCOMPTEXT3: TOSHIBA  VAL3: BAS316  (hidden comment: D)
D5  VAL3: DZ2J110M0L  (hidden comment: SBD)
D6  VAL3: DZ2J056M0L  (hidden comment: SBD)
IC5  USERCOMPTEXT3: TOSHIBA  (hidden comment: TLP785-GR)
IC6  USERCOMPTEXT3: TOSHIBA  (hidden comment: TLP785-GR)
IC7  UCC24624D
IC8  VAL3: TLVH431BIDBZ  (hidden comment: HC086_GATE)
IC9  TLV7211AIDBV
L2  VAL3: ETQP5M2R5YFC  VAL2: 14A  VAL1: 2.5u(M)  (hidden comment: L)
PAD12  TP  (value not drawn)
PAD13  TP  (value not drawn)
PAD14  TP  (value not drawn)
PAD15  TP  (value not drawn)
PAD16  TP  (value not drawn)
PAD17  TP  (value not drawn)
Q5  USERCOMPTEXT3: TOSHIBA  (hidden comment: TPH1R204PL)
Q6  USERCOMPTEXT3: TOSHIBA  (hidden comment: TPH1R204PL)
Q7  USERCOMPTEXT3: TOSHIBA  (hidden comment: 2SC5810)
R48  VAL1: 47(J)  (hidden comment: R)
R51  SIZECODESMD: 2012  VAL1: 4.7(J)  (hidden comment: R)
R52  SIZECODESMD: 2012  VAL1: 4.7(J)  (hidden comment: R)
R53  SIZECODESMD: 2012  VAL1: 10(J)  (hidden comment: R)
R61  SIZECODESMD: 2012  VAL1: 2.2k(J)  (hidden comment: R)
R62  SIZECODESMD: 1608  VAL1: 1k(F)  (hidden comment: R)
R63  SIZECODESMD: 1608  VAL1: 1k(F)  (hidden comment: R)
R64  SIZECODESMD: 1608  VAL1: 18k(F)  (hidden comment: R)
R65  SIZECODESMD: 1608  VAL1: 1.5k(F)  (hidden comment: R)
R66  SIZECODESMD: 1608  VAL1: 12k(F)  (hidden comment: R)
R67  SIZECODESMD: 1608  VAL1: 1.5k(F)  (hidden comment: R)
R71  SIZECODESMD: 1608  VAL1: 33k(F)  (hidden comment: R)
R72  SIZECODESMD: 1608  VAL1: 22k(F)  (hidden comment: R)
R73  SIZECODESMD: 1608  VAL1: 4.7k(F)  (hidden comment: R)
R74  SIZECODESMD: 1608  VAL1: 2.2k(F)  (hidden comment: R)
R75  SIZECODESMD: 2012  VAL1: 0  (hidden comment: R)
TP11  VAL3: LC-22-G  (hidden comment: TP)
TP19  VAL3: LC-22-G  (hidden comment: TP)
U?#2  DATE: 2022/01/18  REVISION: 01  SHEETNUMBER: 2/3  TITLE: 100W LLC DC-DC Converter  DRAWINGNUMBER: RD165-SCHEMATIC-01  (hidden comment: WAKU_DEF100)

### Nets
O_GND: C52.2 C53.2 C56.2 C61.2 C62.2 C63.2 C64.2 C65.2 C66.2 C67.2 C68.2 C69.2 C71.2 C72.2 C73.2 C74.2 CN5.1 IC7.2 IC7.5 PAD14.1 PAD17.1 Q5.S Q6.S R75.1 TP11.1
P-GND: IC5.3 IC6.3  [project net SIG267]
SIG140: C41.2 C45.1 C46.2 D5.1(A) D6.1(A) IC6.2 IC8.3(A2) IC9.5 R67.1 R72.1 R75.2  [also labelled L_GND, SIG142, SIG149, SIG150, SIG152, SIG156, SIG158, SIG226]
SIG214: C56.1 C61.1 C62.1 C63.1 C64.1 C65.1 C66.1 C67.1 C68.1 D4.1(A) L2.1 R65.1 ; off-sheet VSEC  [also labelled SIG270, VSEC]
SIG215: C69.1 C71.1 C72.1 C73.1 C74.1 CN4.1 L2.2 R53.1 R71.1  [also labelled VOUT]
DN000026: C53.1 IC7.7 R53.2
SIG1: IC7.6 PAD15.1 Q6.D R48.1 ; off-sheet SIG1
SIG3: C54.1 IC7.4 PAD12.1 Q5.D ; off-sheet SIG3
SIG4: IC5.4 ; off-sheet SIG4
SIG5: IC6.4 ; off-sheet SIG5
SIG144: C43.1 IC5.2 IC8.2(A0) R63.1 R64.2
SIG154: IC9.3 R71.2 R72.2
SIG160: D5.2(C) Q7.1 R61.2
SIG162: C46.1 D4.2(C) Q7.2 R61.1
SIG166: C52.1 IC7.3
SIG167: IC7.1 R51.2
SIG170: IC7.8 R52.1
SIG172: PAD16.1 Q6.G R52.2
SIG184: IC9.1 R74.2
SIG185: IC6.1 R74.1
SIG210: PAD13.1 Q5.G R51.1
SIG216: R65.2 R66.1
SIG222: D6.2(C) IC9.4 R73.1
SIG225: C42.2 C43.2 IC8.1(A1) R66.2 R67.2
SIG242: IC5.1 R62.1 R63.2
SIG243: C41.1 C45.2 IC9.2 Q7.3 R62.2 R73.2 TP19.1
SIG244: C42.1 R64.1
SIG247: C54.2 R48.2

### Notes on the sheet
- Output & Feed Back

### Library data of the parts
C41 = C#1: as C8 on sheet 1
C42 C43 = C: OriginalSymbolOrigin: (2540,7620); RATEDVOLTAGE: 50; MAXGCOUNT: 1; OUMEMAKER: TDK ＴＤＫ; QUADMODEL: CON_10N; FNLEADFREETHET1GT2GMCTH1: 3_2_N; OUMECLASSIFICATION: セラミックコンデンサ; CDBNAME: Chip1608_GS_1; NOMINALCAPACITA: 10n; PMPRODUCTSTYPEG: HEV; OUMEMAKERKATAMEI: CGA3E2C0G1H103JT@@; CAPACITANCETOLE: J; CDMASTERCADCELG: KC0134; ADSMODELNAME: s_CGA3E2C0G1H103JT@@
C45 C69 = C: as C7 on sheet 1
C46 = C: OriginalSymbolOrigin: (2540,7620); RATEDVOLTAGE: 6.3; MAXGCOUNT: 1; OUMEMAKER: MRT 村田製作所; QUADMODEL: CON_47U; FNLEADFREETHET1GT2GMCTH1: 3_0_N; OUMECLASSIFICATION: セラミックコンデンサ; CDBNAME: Chip3225_GS; NOMINALCAPACITA: 47u; PMPRODUCTSTYPEG: HEV; OUMEMAKERKATAMEI: GCM32ER70J476ME19L@@; CAPACITANCETOLE: M; CDMASTERCADCELG: KC0138; ADSMODELNAME: s_GCM32ER70J476ME19L@@
C52 = C: OriginalSymbolOrigin: (2540,7620); RATEDVOLTAGE: 50; MAXGCOUNT: 1; OUMEMAKER: MRT 村田製作所; QUADMODEL: CON_2.2U; FNLEADFREETHET1GT2GMCTH1: 3_2_N; OUMECLASSIFICATION: セラミックコンデンサ; CDBNAME: Chip3216_GS_1; NOMINALCAPACITA: 2.2u; PMPRODUCTSTYPEG: HEV; OUMEMAKERKATAMEI: GCM31CR71H225KA55L@@; CAPACITANCETOLE: K; CDMASTERCADCELG: KC0137; ADSMODELNAME: s_GCM31CR71H225KA55L@@
C53 = C#1: OriginalSymbolOrigin: (2540,7620); CaptureCellPackProp: C##1; RATEDVOLTAGE: 50; MAXGCOUNT: 1; OUMEMAKER: MRT 村田製作所; QUADMODEL: CON_2.2U; FNLEADFREETHET1GT2GMCTH1: 3_2_N; OUMECLASSIFICATION: セラミックコンデンサ; CDBNAME: Chip3216_GS_1; NOMINALCAPACITA: 2.2u; PMPRODUCTSTYPEG: HEV; OUMEMAKERKATAMEI: GCM31CR71H225KA55L@@; CAPACITANCETOLE: K; CDMASTERCADCELG: KC0137; ADSMODELNAME: s_GCM31CR71H225KA55L@@
C54 = C: OriginalSymbolOrigin: (2540,7620); CDBNAME: ECQE2**3*F_PN
C56 = C#1: OriginalSymbolOrigin: (2540,7620); CaptureCellPackProp: C##1; CDBNAME: PCR1****MCL1GS_NC
C61-C68 = C#1: OriginalSymbolOrigin: (2540,7620); CaptureCellPackProp: C##1; RATEDVOLTAGE: 6.3; MAXGCOUNT: 1; TEMPCHARACTERI2: B; OUMEMAKER: TYD 太陽誘電; QUADMODEL: CON_47U; FNLEADFREETHET1GT2GMCTH1: 3_0_N; OUMECLASSIFICATION: セラミックコンデンサ; CDBNAME: Chip3225_GS; NOMINALCAPACITA: 47u; PMPRODUCTSTYPEG: SV1; OUMEMAKERKATAMEI: JMK325BJ476MM-T; CAPACITANCETOLE: M; CDMASTERCADCELG: DC903A; ADSMODELNAME: s_JMK325BJ476MM_T
C71-C74 = C: OriginalSymbolOrigin: (2540,7620); RATEDVOLTAGE: 6.3; MAXGCOUNT: 1; TEMPCHARACTERI2: B; OUMEMAKER: TYD 太陽誘電; QUADMODEL: CON_47U; FNLEADFREETHET1GT2GMCTH1: 3_0_N; OUMECLASSIFICATION: セラミックコンデンサ; CDBNAME: Chip3225_GS; NOMINALCAPACITA: 47u; PMPRODUCTSTYPEG: SV1; OUMEMAKERKATAMEI: JMK325BJ476MM-T; CAPACITANCETOLE: M; CDMASTERCADCELG: DC903A; ADSMODELNAME: s_JMK325BJ476MM_T
CN4 CN5 = C1A: OUMEPARTTYPE: CN; SAVEAREA0: -2398,-158,22444,15662; SAVECOUNT: 23; TIME: 13:28:28; UPDATEUSER: 19910145; UPDATETIME: 08:46:11; OriginalSymbolOrigin: (5080,12700); RATEDCURRENT: 0; MAXGCOUNT: 1; OUMEMAKER: AMP タイコエレクトロニクスアンプ; FNLEADFREETHET1GT2GMCTH1: N_N_N; OUMECLASSIFICATION: プリント板用角形コネクタ; CDBNAME: 8237-0-05-**-00-00-03-0_ML; OUMEMAKERKATAMEI: 87220-1; CDMASTERCADCELG: CUK0165
D4 = D: SAVEAREA0: -225,-91,12804,7836; SAVECOUNT: 3; TIME: 14:49:55; UPDATEUSER: 19870035; UPDATETIME: 14:20:16; OriginalSymbolOrigin: (5080,5080); CDBNAME: BAS316_TS_A
D5 = SBD: SAVEAREA0: -4630,-153,17114,13055; TIME: 14:49:55; UPDATEUSER: fukuda-y; UPDATETIME: 08:16:22; SAVECOUNT: 9; OriginalSymbolOrigin: (5080,5080); CDBNAME: DZ2J110M0L_PN_A
D6 = SBD: SAVEAREA0: -4630,-153,17114,13055; TIME: 14:49:55; UPDATEUSER: fukuda-y; UPDATETIME: 08:16:22; SAVECOUNT: 9; OriginalSymbolOrigin: (5080,5080); CDBNAME: DZ2J056*0L_PN_A
IC5 IC6 = TLP785-GR: SAVEAREA0: -14986,-1554,37270,22534; TIME: 18:29:30; UPDATEUSER: t5459927; UPDATETIME: 17:04:25; SAVECOUNT: 2; OriginalSymbolOrigin: (5080,17780); CDBNAME: TLP785_TS_1
IC7 = UCC24624D: TIME: 09:07:35; UPDATEUSER: t5459927; UPDATETIME: 09:15:01; SAVECOUNT: 2; SAVEAREA0: -23382,-806,66635,38817; OriginalSymbolOrigin: (7620,35560); CDBNAME: UCC24624D*_TI
IC8 = HC086_GATE: OUMEPARTTYPE: IC; SAVEAREA0: -52989,-44408,93321,62857; TIME: 17:36:35; UPDATEUSER: t5459927; UPDATETIME: 16:48:34; SAVECOUNT: 2; OriginalSymbolOrigin: (7620,15240); MAXGCOUNT: 4; OUMEMAKER: TSB 東芝; GCOUNT: 1; MOUNTINGFORMSMD: SMD; FNLEADFREETHET1GT2GMCTH1: N_N_N; OUMECLASSIFICATION: CMOSロジック; CDBNAME: TLVH43***DBZ*_TI; PROCESS: 74HC; OUMEMAKERKATAMEI: TC74HC86F; CDMASTERCADCELG: DI830B
IC9 = TLV7211AIDBV: as IC4 on sheet 1
L2 = L: OriginalSymbolOrigin: (2540,5080); CDBNAME: ETQP5M***YFC_PN
PAD12-PAD17 = TP: as PAD2 on sheet 1
Q5 Q6 = TPH1R204PL: SAVEAREA0: -12325,8914,25768,24851; TIME: 18:57:44; UPDATEUSER: t5459927; UPDATETIME: 15:06:39; SAVECOUNT: 19; OriginalSymbolOrigin: (2540,20320); CDBNAME: TPH1R204PL_TS_A
Q7 = 2SC5810: DEVICENAME: 2SC2712-Y; SAVECOUNT: 8; SAVEAREA0: -35656,-18339,48402,18661; TIME: 17:21:57; UPDATEUSER: t5459927; UPDATETIME: 15:35:42; OriginalSymbolOrigin: (2540,10160); CDBNAME: 2SC5810_TS
R48 = R: OriginalSymbolOrigin: (5080,5080); VAL2: 1W; CDBNAME: MOS1C****_GS_1
R51 R52 = R: OriginalSymbolOrigin: (5080,5080); MAXGCOUNT: 1; OUMEMAKER: HDK 北陸電気工業; QUADMODEL: RES_4.7; MOUNTINGFORMSMD: SMD; FNLEADFREETHET1GT2GMCTH1: N_N_N; OUMECLASSIFICATION: 表面実装用固定抵抗器; CDBNAME: Chip2012_GS_1; RESISTANCETOLER: J; POWERRATING: 100m; OUMEMAKERKATAMEI: CR1/10 4R7JV; NOMINALRESISTAN: 4.7; VAL2: 400mW; CDMASTERCADCELG: DR910A; ADSMODELNAME: s_CR1_10_4R7JV
R53 = R: as R31 on sheet 1
R61 = R: as R3 on sheet 1
R62 R63 = R: OriginalSymbolOrigin: (5080,5080); MAXGCOUNT: 1; OUMEMAKER: KOA コーア; QUADMODEL: RES_1K; MOUNTINGFORMSMD: SMD; FNLEADFREETHET1GT2GMCTH1: N_N_N; OUMECLASSIFICATION: 表面実装用固定抵抗器; CDBNAME: Chip1608_GS_1; RESISTANCETOLER: F; PMPRODUCTSTYPEG: DME; POWERRATING: 100m; OUMEMAKERKATAMEI: RK73H1JRTTD1001F; NOMINALRESISTAN: 1K; VAL2: 100mW; CDMASTERCADCELG: KC0008; ADSMODELNAME: s_RK73H1JRTTD1001F
R64 = R#1: OriginalSymbolOrigin: (5080,5080); CaptureCellPackProp: R##1; MAXGCOUNT: 1; OUMEMAKER: ROH ロー・; QUADMODEL: RES_18K; MOUNTINGFORMSMD: SMD; FNLEADFREETHET1GT2GMCTH1: 3_1_N; OUMECLASSIFICATION: 表面実装用固定抵抗器; CDBNAME: Chip1608_GS_1; RESISTANCETOLER: F; POWERRATING: 63m; OUMEMAKERKATAMEI: MCR03EZPFX1802; NOMINALRESISTAN: 18K; VAL2: 100mW; CDMASTERCADCELG: DR802R; ADSMODELNAME: s_MCR03EZPFX1802
R65 R67 = R: OriginalSymbolOrigin: (5080,5080); MAXGCOUNT: 1; OUMEMAKER: HDK 北陸電気工業; QUADMODEL: RES_1.5K; MOUNTINGFORMSMD: SMD; FNLEADFREETHET1GT2GMCTH1: 3_1_N; OUMECLASSIFICATION: 表面実装用固定抵抗器; CDBNAME: Chip1608_GS_1; RESISTANCETOLER: F; POWERRATING: 63m; OUMEMAKERKATAMEI: CR1/16 152FV; NOMINALRESISTAN: 1.5K; VAL2: 100mW; CDMASTERCADCELG: DR802R; ADSMODELNAME: s_CR1_16_152FV
R66 = R: OriginalSymbolOrigin: (5080,5080); MAXGCOUNT: 1; OUMEMAKER: HDK 北陸電気工業; QUADMODEL: RES_12K; MOUNTINGFORMSMD: SMD; FNLEADFREETHET1GT2GMCTH1: 3_1_N; OUMECLASSIFICATION: 表面実装用固定抵抗器; CDBNAME: Chip1608_GS_1; RESISTANCETOLER: F; POWERRATING: 63m; OUMEMAKERKATAMEI: CR1/16 123FV; NOMINALRESISTAN: 12K; VAL2: 100mW; CDMASTERCADCELG: DR802R; ADSMODELNAME: s_CR1_16_123FV
R71 = R: OriginalSymbolOrigin: (5080,5080); MAXGCOUNT: 1; OUMEMAKER: ROH ロー・; QUADMODEL: RES_33K; MOUNTINGFORMSMD: SMD; FNLEADFREETHET1GT2GMCTH1: 3_1_N; OUMECLASSIFICATION: 表面実装用固定抵抗器; CDBNAME: Chip1608_GS_1; RESISTANCETOLER: F; POWERRATING: 63m; OUMEMAKERKATAMEI: MCR03EZPFX3302; NOMINALRESISTAN: 33K; VAL2: 100mW; CDMASTERCADCELG: DR802R; ADSMODELNAME: s_MCR03EZPFX3302
R72 = R: as R43 on sheet 1
R73 = R: as R41 on sheet 1
R74 = R: OriginalSymbolOrigin: (5080,5080); MAXGCOUNT: 1; OUMEMAKER: KOA コーア; QUADMODEL: RES_2.2K; MOUNTINGFORMSMD: SMD; FNLEADFREETHET1GT2GMCTH1: 3_1_N; OUMECLASSIFICATION: 表面実装用固定抵抗器; CDBNAME: Chip1608_GS_1; RESISTANCETOLER: F; PMPRODUCTSTYPEG: HEV; POWERRATING: 100m; OUMEMAKERKATAMEI: RK73H1JTTD2201F@@; NOMINALRESISTAN: 2.2K; VAL2: 100mW; CDMASTERCADCELG: KC0133; ADSMODELNAME: s_RK73H1JTTD2201F@@
R75 = R#1: OriginalSymbolOrigin: (5080,5080); CaptureCellPackProp: R##1; MAXGCOUNT: 1; OUMEMAKER: KOA コーア; QUADMODEL: RES_0; MOUNTINGFORMSMD: SMD; FNLEADFREETHET1GT2GMCTH1: 3_2_N; OUMECLASSIFICATION: 表面実装用固定抵抗器; CDBNAME: Chip2012_GS_1; RESISTANCETOLER: X; PMPRODUCTSTYPEG: DME-PC1; POWERRATING: 125m; OUMEMAKERKATAMEI: RK73Z2ATTD; VAL2: 400mW; CDMASTERCADCELG: KCK0211; ADSMODELNAME: s_RK73Z2ATTD
TP11 TP19 = TP: as TP1 on sheet 1
U?#2 = WAKU_DEF100: PLOTTIME: HH:MM; SAVEAREA0: 198008,-65938,436964,90161; TIME: 14:30:25; UPDATEUSER: t5459927; UPDATETIME: 11:02:38; SAVECOUNT: 4; OriginalSymbolOrigin: (10160,284480)

## Sheet 3.SchDoc
size 420 x 297 mm
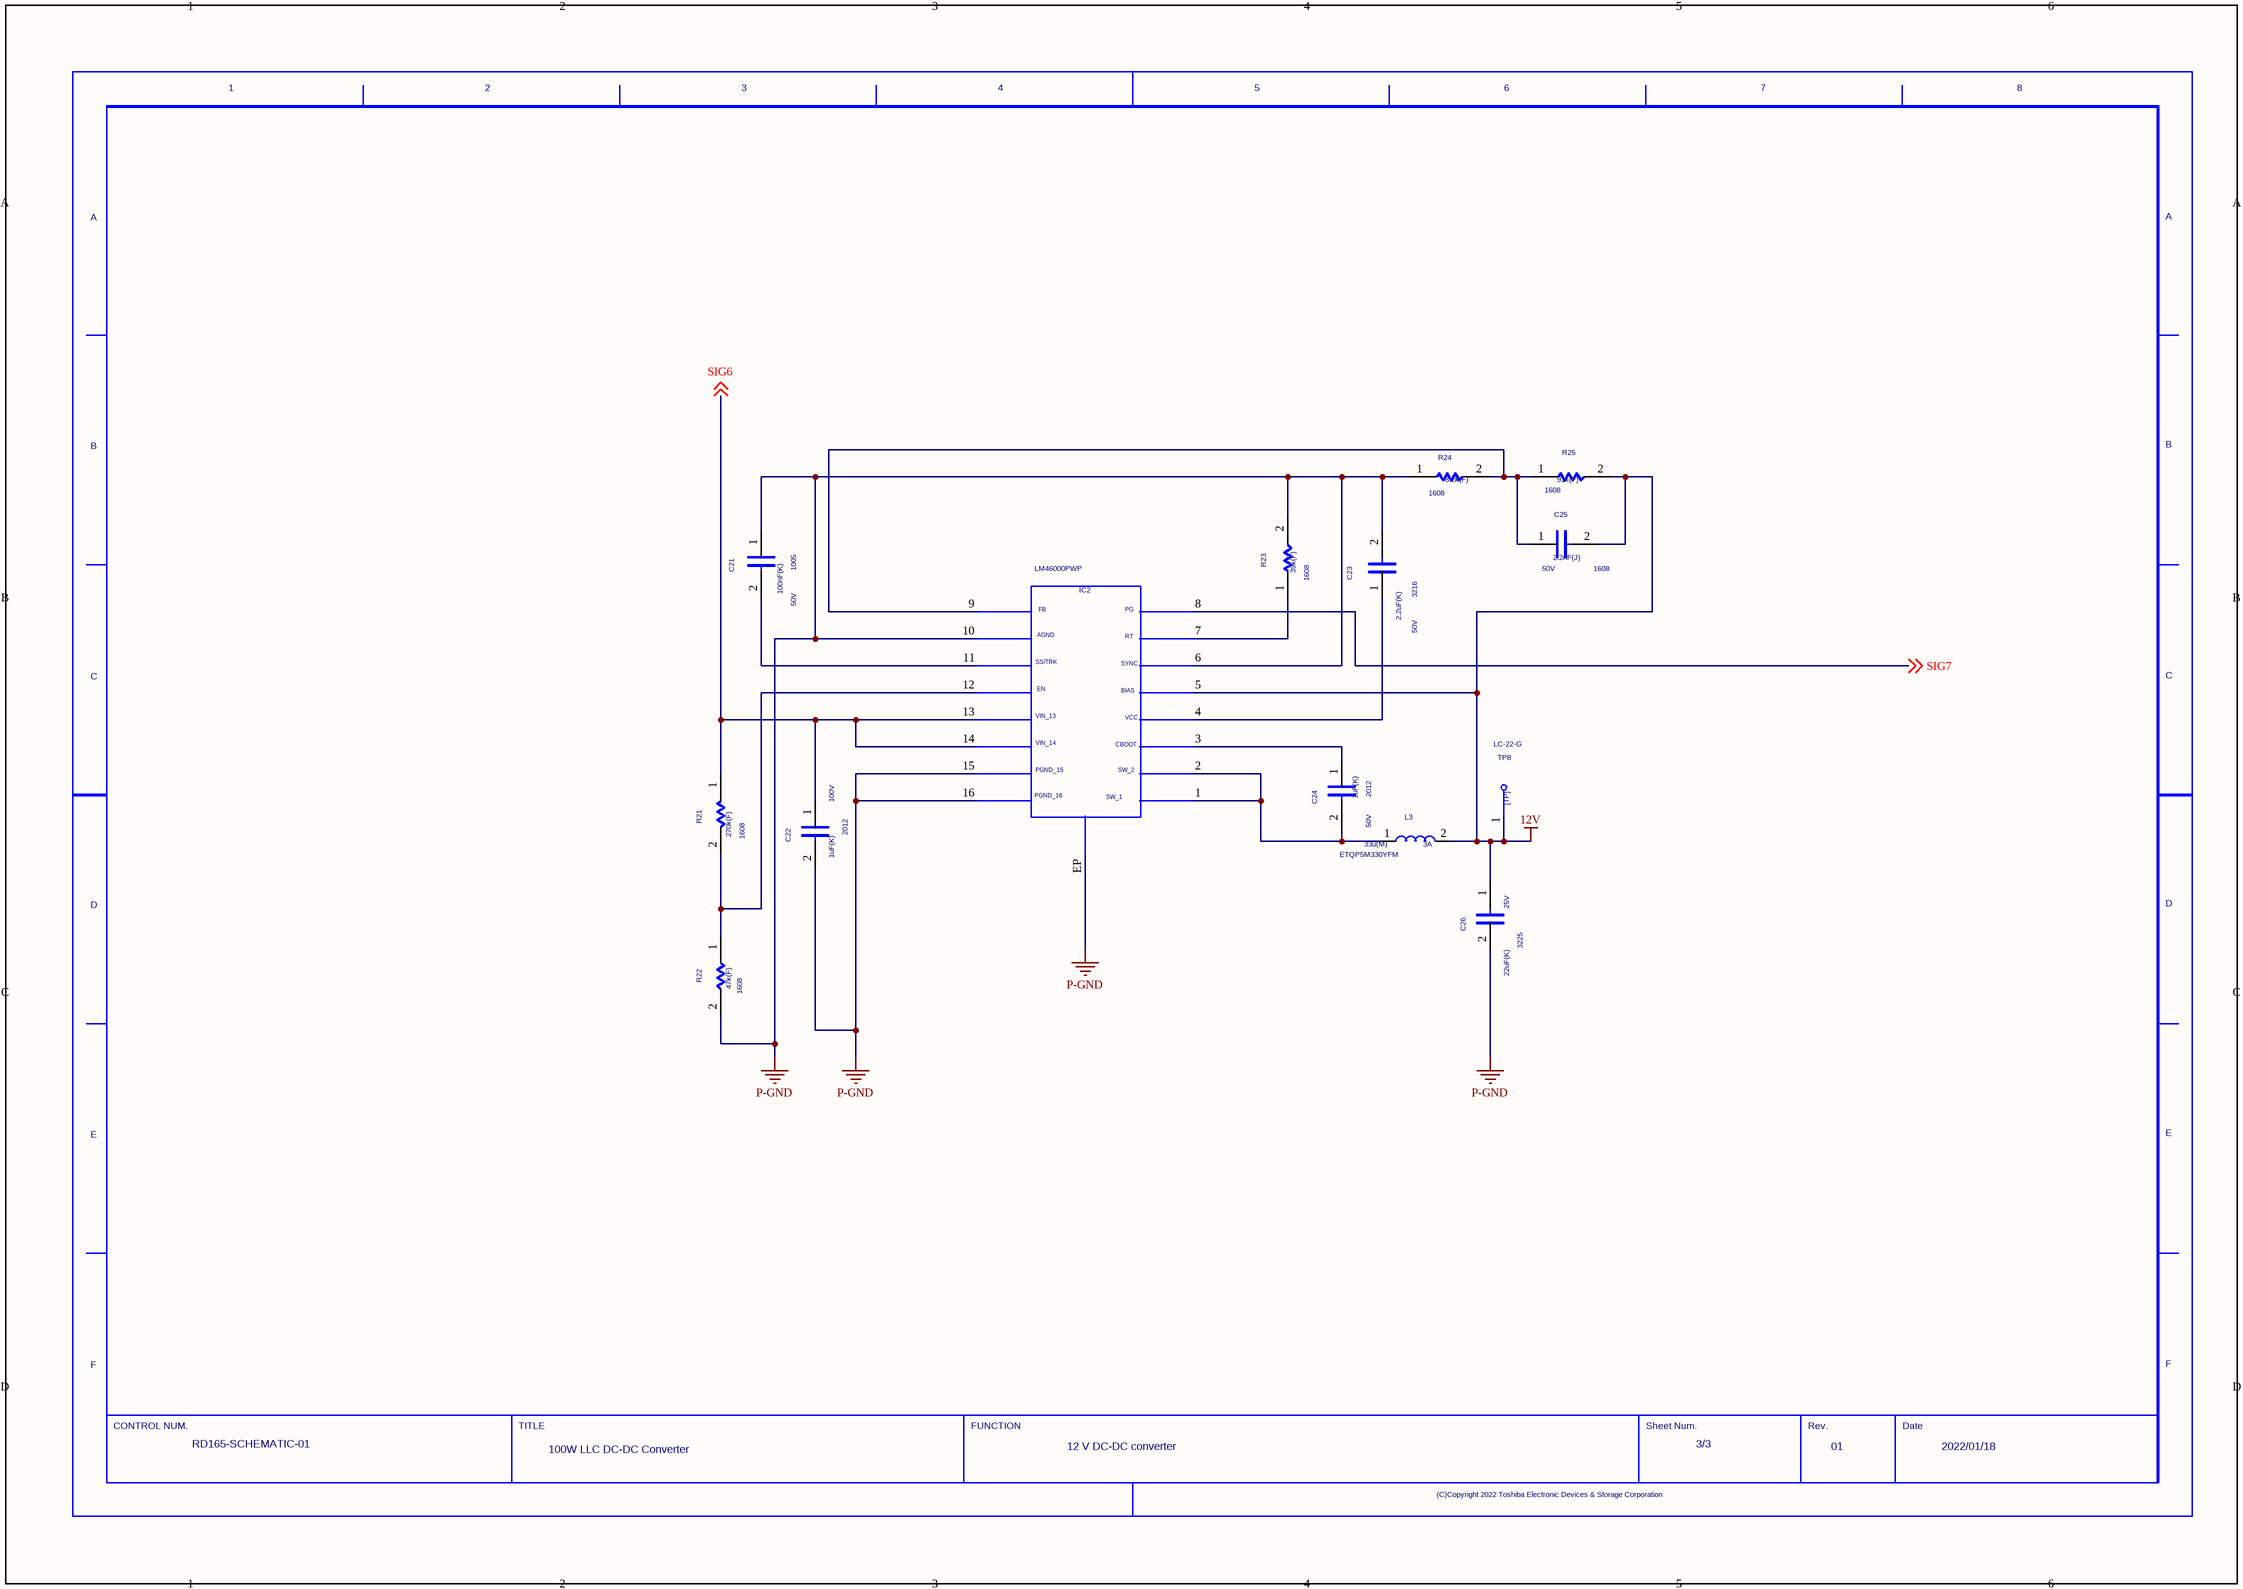
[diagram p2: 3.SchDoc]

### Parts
(Parts that share a designator on the sheet are numbered #1, #2 ... from top to bottom, then left to right.)
C21  SIZECODESMD: 1005  VAL2: 50V  VAL1: 100nF(K)  (hidden comment: C)
C22  SIZECODESMD: 2012  VAL2: 100V  VAL1: 1uF(K)  (hidden comment: C)
C23  SIZECODESMD: 3216  VAL2: 50V  VAL1: 2.2uF(K)  (hidden comment: C)
C24  SIZECODESMD: 2012  VAL2: 50V  VAL1: 1uF(K)  (hidden comment: C)
C25  SIZECODESMD: 1608  VAL2: 50V  VAL1: 2.2nF(J)  (hidden comment: C)
C26  SIZECODESMD: 3225  VAL2: 25V  VAL1: 22uF(K)  (hidden comment: C)
IC2  LM46000PWP
L3  VAL3: ETQP5M330YFM  VAL2: 3A  VAL1: 33u(M)  (hidden comment: L)
R21  SIZECODESMD: 1608  VAL1: 270k(F)  (hidden comment: R)
R22  SIZECODESMD: 1608  VAL1: 47k(F)  (hidden comment: R)
R23  SIZECODESMD: 1608  VAL1: 39k(F)  (hidden comment: R)
R24  SIZECODESMD: 1608  VAL1: 8.2k(F)  (hidden comment: R)
R25  SIZECODESMD: 1608  VAL1: 91k(F)  (hidden comment: R)
TP8  VAL3: LC-22-G  (hidden comment: TP)
U?#3  DATE: 2022/01/18  FUNCTION: 12 V DC-DC converter  REVISION: 01  SHEETNUMBER: 3/3  TITLE: 100W LLC DC-DC Converter  DRAWINGNUMBER: RD165-SCHEMATIC-01  (hidden comment: WAKU_DEF100)

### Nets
12V: C25.2 C26.1 IC2.5 L3.2 R25.2 TP8.1  [also labelled SIG252]  [project net SIG104]
P-GND: C21.1 C22.2 C23.2 C26.2 IC2.6 IC2.10 IC2.15 IC2.16 IC2.EP R22.2 R23.2 R24.1  [project net SIG267]
SIG6: C22.1 IC2.13 IC2.14 R21.1 ; off-sheet SIG6
SIG7: IC2.8 ; off-sheet SIG7
SIG250: C23.1 IC2.4
SIG251: IC2.7 R23.1
SIG254: C21.2 IC2.11
SIG256: IC2.12 R21.2 R22.1
SIG257: C25.1 IC2.9 R24.2 R25.1
SIG258: C24.2 IC2.1 IC2.2 L3.1
SIG259: C24.1 IC2.3

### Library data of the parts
C21 = C: OriginalSymbolOrigin: (2540,7620); RATEDVOLTAGE: 50; MAXGCOUNT: 1; TEMPCHARACTERI2: B; OUMEMAKER: TDK ＴＤＫ; QUADMODEL: CON_100N; FNLEADFREETHET1GT2GMCTH1: N_N_N; OUMECLASSIFICATION: セラミックコンデンサ; CDBNAME: Chip1005_GS_2; NOMINALCAPACITA: 100n; OUMEMAKERKATAMEI: C1005JB0J104KT; CAPACITANCETOLE: K; CDMASTERCADCELG: DC834K; ADSMODELNAME: s_C1005JB0J104KT
C22 C24 = C: as C7 on sheet 1
C23 = C: as C52 on sheet 2
C25 = C: OriginalSymbolOrigin: (2540,7620); RATEDVOLTAGE: 50; MAXGCOUNT: 1; TEMPCHARACTERI2: CH; OUMEMAKER: MRT 村田製作所; QUADMODEL: CON_2.2N; FNLEADFREETHET1GT2GMCTH1: N_N_N; OUMECLASSIFICATION: セラミックコンデンサ; CDBNAME: Chip1608_GS_1; NOMINALCAPACITA: 2.2n; PMPRODUCTSTYPEG: DA; OUMEMAKERKATAMEI: GRM1882C1H222JA01D@@; CAPACITANCETOLE: J; ADSMODELNAME: s_GRM1882C1H222JA01D@@
C26 = C#1: OriginalSymbolOrigin: (2540,7620); CaptureCellPackProp: C##1; RATEDVOLTAGE: 16; MAXGCOUNT: 1; OUMEMAKER: TDK ＴＤＫ; QUADMODEL: CON_22U; FNLEADFREETHET1GT2GMCTH1: N_N_N; OUMECLASSIFICATION: セラミックコンデンサ; CDBNAME: Chip3225_GS; NOMINALCAPACITA: 22u; OUMEMAKERKATAMEI: (SV)C3225X7R1C226K250AC; CAPACITANCETOLE: K; CDMASTERCADCELG: KCK0271; ADSMODELNAME: s__SV_C3225X7R1C226K250AC
IC2 = LM46000PWP: SAVEAREA0: -78128,-18763,121485,85972; SAVECOUNT: 11; TIME: 10:30:02; UPDATEUSER: t5459927; UPDATETIME: 09:42:03; OriginalSymbolOrigin: (0,45720); CDBNAME: LM46000PWP_GS
L3 = L: OriginalSymbolOrigin: (2540,5080); CDBNAME: ETQP5M***Y*M_PN
R21 = R: OriginalSymbolOrigin: (5080,5080); MAXGCOUNT: 1; OUMEMAKER: KOA コーア; QUADMODEL: RES_270K; MOUNTINGFORMSMD: SMD; FNLEADFREETHET1GT2GMCTH1: 3_1_N; OUMECLASSIFICATION: 表面実装用固定抵抗器; CDBNAME: Chip1608_GS_1; RESISTANCETOLER: D; PMPRODUCTSTYPEG: HEV; POWERRATING: 100m; OUMEMAKERKATAMEI: RK73H1JTTD2703D@@; NOMINALRESISTAN: 270K; VAL2: 100mW; CDMASTERCADCELG: KC0133; ADSMODELNAME: s_RK73H1JTTD2703D@@
R22 = R: OriginalSymbolOrigin: (5080,5080); MAXGCOUNT: 1; OUMEMAKER: KOA コーア; QUADMODEL: RES_47K; MOUNTINGFORMSMD: SMD; FNLEADFREETHET1GT2GMCTH1: 3_1_N; OUMECLASSIFICATION: 表面実装用固定抵抗器; CDBNAME: Chip1608_GS_1; RESISTANCETOLER: F; POWERRATING: 63m; OUMEMAKERKATAMEI: RK73H1JTD4702F; NOMINALRESISTAN: 47K; VAL2: 100mW; CDMASTERCADCELG: DR802R; ADSMODELNAME: s_RK73H1JTD4702F
R23 = R: OriginalSymbolOrigin: (5080,5080); MAXGCOUNT: 1; OUMEMAKER: HDK 北陸電気工業; QUADMODEL: RES_39K; MOUNTINGFORMSMD: SMD; FNLEADFREETHET1GT2GMCTH1: 3_1_N; OUMECLASSIFICATION: 表面実装用固定抵抗器; CDBNAME: Chip1608_GS_1; RESISTANCETOLER: F; POWERRATING: 63m; OUMEMAKERKATAMEI: CR1/16 393FV; NOMINALRESISTAN: 39K; VAL2: 100mW; CDMASTERCADCELG: DR802R; ADSMODELNAME: s_CR1_16_393FV
R24 = R: OriginalSymbolOrigin: (5080,5080); MAXGCOUNT: 1; OUMEMAKER: KOA コーア; QUADMODEL: RES_8.2K; MOUNTINGFORMSMD: SMD; FNLEADFREETHET1GT2GMCTH1: N_N_N; OUMECLASSIFICATION: 表面実装用固定抵抗器; CDBNAME: Chip1608_GS_1; RESISTANCETOLER: F; PMPRODUCTSTYPEG: DME; POWERRATING: 100m; OUMEMAKERKATAMEI: RK73H1JRTTD8201F; NOMINALRESISTAN: 8.2K; VAL2: 100mW; CDMASTERCADCELG: KCK0203; ADSMODELNAME: s_RK73H1JRTTD8201F
R25 = R: OriginalSymbolOrigin: (5080,5080); MAXGCOUNT: 1; OUMEMAKER: NAE パナソニックエレクトロニックデバイス; QUADMODEL: RES_91K; MOUNTINGFORMSMD: SMD; FNLEADFREETHET1GT2GMCTH1: N_N_N; OUMECLASSIFICATION: 表面実装用固定抵抗器; CDBNAME: Chip1608_GS_1; RESISTANCETOLER: F; PMPRODUCTSTYPEG: DA; POWERRATING: 100m; OUMEMAKERKATAMEI: ERJ3EKF9102V@@; NOMINALRESISTAN: 91K; VAL2: 100mW; CDMASTERCADCELG: KC0161; ADSMODELNAME: s_ERJ3EKF9102V@@
TP8 = TP: as TP1 on sheet 1
U?#3 = WAKU_DEF100: PLOTTIME: HH:MM; SAVEAREA0: 198008,-65938,436964,90161; TIME: 14:30:25; UPDATEUSER: t5459927; UPDATETIME: 11:03:12; SAVECOUNT: 4; OriginalSymbolOrigin: (10160,284480)

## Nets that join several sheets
O_GND: 1 (C51.2), 2 (25 pins)
SIG104: 1 (8 pins), 3 (6 pins)
SIG214: 1 (T1.7 T1.9), 2 (12 pins)
SIG267: 1 (32 pins), 2 (IC5.3 IC6.3), 3 (12 pins)
SIG1: 1 (T1.10), 2 (IC7.6 PAD15.1 Q6.D R48.1)
SIG3: 1 (T1.6), 2 (C54.1 IC7.4 PAD12.1 Q5.D)
SIG4: 1 (R38.2), 2 (IC5.4)
SIG5: 1 (IC4.4 R41.1 R42.2), 2 (IC6.4)
SIG6: 1 (Q3.2), 3 (C22.1 IC2.13 IC2.14 R21.1)
SIG7: 1 (C32.2 IC3.4 Q8.D), 3 (IC2.8)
